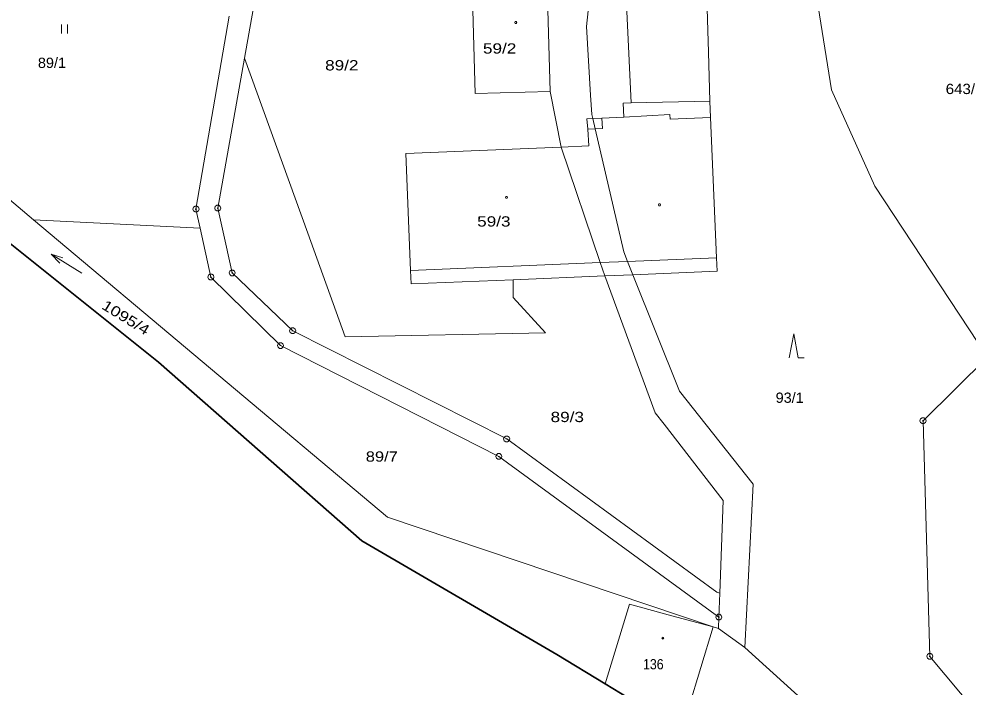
# Model space of a CAD drawing. Extents: x -687390 to -684106, y -954833 to -951648.
# Drawn here: x -687306.4 to -687149.2, y -953102.7 to -952992 of the extents above; entities that cross this region are included whole.
import ezdxf

# ---------------------------------------------------------------- set-up
doc = ezdxf.new("R2010")
doc.units = 0
doc.header["$LTSCALE"] = 0.68
doc.header["$PDMODE"] = 32
doc.header["$PDSIZE"] = 0.34
for name, color, linetype, lineweight in [('1', 7, 'Continuous', 13), ('3', 7, 'Continuous', 13), ('4', 7, 'Continuous', 13), ('5', 7, 'Continuous', 13), ('8', 7, 'Continuous', 13)]:
    doc.layers.add(name, color=color, linetype=linetype, lineweight=lineweight)
doc.layers.add('2', color=7, linetype='Continuous')

msp = doc.modelspace()

# ---------------------------------------------------------------- linework, layer by layer
at = {"layer": '1'}
for p, q in [((-687171.85, -953003.77), (-687180.3, -952950.89)), ((-687218.99, -952983.29), (-687218.44, -953004.04)), ((-687231.39, -952983.63), (-687230.83, -953004.38)), ((-687277.05, -953023.53), (-687271.54, -952991.58)), ((-687269.03, -952998.54), (-687273.44, -953023.38)), ((-687258.55, -953027.54), (-687269.03, -952998.54)), ((-687230.83, -953004.38), (-687218.44, -953004.04)), ((-687218.44, -953004.04), (-687216.6, -953013.27)), ((-687191.97, -953005.64), (-687191.86, -953008.35)), ((-687211.36, -953008.54), (-687211.52, -953007.83)), ((-687216.6, -953013.27), (-687210.15, -953032.4)), ((-687276.37, -953026.67), (-687303.95, -953025.31)), ((-687258.55, -953027.54), (-687252.33, -953044.71)), ((-687205.61, -953032.21), (-687206.24, -953030.62)), ((-687241.52, -953033.71), (-687241.43, -953035.93)), ((-687190.78, -953033.82), (-687204.73, -953034.41)), ((-687224.52, -953035.23), (-687224.56, -953038.19)), ((-687224.56, -953038.19), (-687219.21, -953044.02)), ((-687252.33, -953044.71), (-687219.21, -953044.02)), ((-687184.78, -953069.1), (-687197, -953053.68)), ((-687226.9, -953064.53), (-687190.48, -953091.15)), ((-687209.3, -953102.21), (-687205.27, -953088.97)), ((-687198.26, -953090.92), (-687205.27, -953088.97)), ((-687198.26, -953090.92), (-687191.42, -953092.75)), ((-687190.48, -953091.15), (-687190.55, -953093.04)), ((-687196.64, -953109.91), (-687191.42, -953092.75)), ((-687190.55, -953093.04), (-687186.21, -953096.15))]:
    msp.add_line(p, q, dxfattribs=at)
at = {"layer": '1', "lineweight": 35}
for p, q in [((-687283.27, -953048.91), (-687343.63, -953000.56)), ((-687283.27, -953048.91), (-687249.6, -953078.52)), ((-687217.33, -953097.33), (-687249.6, -953078.52)), ((-687217.33, -953097.33), (-687209.3, -953102.21))]:
    msp.add_line(p, q, dxfattribs=at)
at = {"layer": '1'}
for points in [[(-687269.03, -952998.54), (-687263.99, -952970.24), (-687261.03, -952965.73), (-687259.43, -952963.28)], [(-687212.39, -952993.27), (-687211.72, -952986.95), (-687215.35, -952976.69)], [(-687191.97, -953005.64), (-687192.2, -952997.53), (-687192.74, -952979.44)], [(-687211.52, -953007.83), (-687211.71, -953004.66), (-687212.39, -952993.27)], [(-687171.85, -953003.77), (-687164.64, -953019.72), (-687146.01, -953048.09), (-687124.1, -953070.77)], [(-687211.36, -953008.54), (-687210.97, -953010.24), (-687206.24, -953030.62)], [(-687190.78, -953033.82), (-687190.88, -953031.6), (-687191.86, -953008.35)], [(-687245.33, -953074.55), (-687303.95, -953025.31), (-687321.79, -953010.21)], [(-687216.6, -953013.27), (-687242.32, -953014.34), (-687241.52, -953033.71)], [(-687277.05, -953023.53), (-687276.37, -953026.67), (-687274.58, -953034.79), (-687263.05, -953046.15), (-687226.9, -953064.53)], [(-687225.61, -953061.62), (-687261.04, -953043.7), (-687271.06, -953034.1), (-687272.67, -953026.85), (-687273.44, -953023.38)], [(-687197, -953053.68), (-687204.73, -953034.41), (-687205.61, -953032.21)], [(-687210.15, -953032.4), (-687209.34, -953034.6), (-687201.01, -953057.26)], [(-687209.34, -953034.6), (-687224.52, -953035.23), (-687241.43, -953035.93)], [(-687146.01, -953048.09), (-687156.68, -953058.6), (-687155.56, -953097.64), (-687150.48, -953103.71), (-687143.97, -953111.49), (-687139.25, -953122.31), (-687131.65, -953139.03), (-687139.9, -953147.82), (-687145.6, -953153.05), (-687131.15, -953173.98), (-687112.27, -953196.97), (-687095.24, -953216.13), (-687090.69, -953245), (-687097.15, -953266.61)], [(-687201.01, -953057.26), (-687199.54, -953059.18), (-687189.78, -953071.81)], [(-687190.34, -953087.17), (-687190.8, -953086.99), (-687225.61, -953061.62)], [(-687168, -953112.71), (-687186.21, -953096.15), (-687184.78, -953069.1)], [(-687189.78, -953071.81), (-687190.34, -953087.17), (-687190.48, -953091.15)], [(-687245.33, -953074.55), (-687191.42, -953092.75), (-687190.55, -953093.04)]]:
    msp.add_lwpolyline(points, dxfattribs=at)
at = {"layer": '1', "lineweight": 35}
msp.add_lwpolyline([(-687180.98, -953119.45), (-687196.64, -953109.91), (-687209.3, -953102.21)], dxfattribs=at)
at = {"layer": '3'}
for p, q in [((-687299.34, -952992.96), (-687299.34, -952994.46)), ((-687298.34, -952994.46), (-687298.34, -952992.96)), ((-687295.938, -953034.157), (-687301.042, -953031.003))]:
    msp.add_line(p, q, dxfattribs=at)
for points in [[(-687299.604, -953032.48), (-687301.042, -953031.003), (-687299.078, -953031.629)], [(-687178.84, -953048.2), (-687178.09, -953044.2), (-687177.34, -953048.2), (-687176.34, -953048.2)]]:
    msp.add_lwpolyline(points, dxfattribs=at)
at = {"layer": '4'}
for p, q in [((-687191.97, -953005.64), (-687204.98, -953005.92)), ((-687212.18, -953010.3), (-687212.04, -953013.07)), ((-687212.04, -953013.07), (-687216.6, -953013.27)), ((-687205.61, -953032.21), (-687210.15, -953032.4)), ((-687190.88, -953031.6), (-687205.61, -953032.21)), ((-687210.15, -953032.4), (-687241.52, -953033.71)), ((-687204.73, -953034.41), (-687209.34, -953034.6))]:
    msp.add_line(p, q, dxfattribs=at)
for points in [[(-687215.9, -952960.52), (-687214.88, -952960.48), (-687214.4, -952977), (-687206.4, -952976.76), (-687204.98, -953005.92), (-687206.34, -953005.99), (-687206.22, -953008.27), (-687198.6, -953007.86)], [(-687209.84, -953008.46), (-687211.36, -953008.54), (-687212.36, -953008.59), (-687212.18, -953010.3)], [(-687206.22, -953008.27), (-687209.84, -953008.46), (-687209.75, -953010.18)], [(-687191.86, -953008.35), (-687198.56, -953008.64), (-687198.6, -953007.86)], [(-687209.75, -953010.18), (-687210.97, -953010.24), (-687212.18, -953010.3)]]:
    msp.add_lwpolyline(points, dxfattribs=at)
at = {"layer": '5'}
for points in [[(-687224.02, -952992.47), (-687223.93, -952992.62), (-687224.02, -952992.77), (-687224.2, -952992.77), (-687224.29, -952992.62), (-687224.2, -952992.47)], [(-687225.55, -953021.42), (-687225.46, -953021.57), (-687225.55, -953021.72), (-687225.73, -953021.72), (-687225.82, -953021.57), (-687225.73, -953021.42)], [(-687200.23, -953022.68), (-687200.14, -953022.83), (-687200.23, -953022.98), (-687200.41, -953022.98), (-687200.5, -953022.83), (-687200.41, -953022.68)]]:
    msp.add_lwpolyline(points, close=True, dxfattribs=at)
msp.add_point((-687199.76, -953094.63), dxfattribs=at)
at = {"layer": '8'}
for p, q in [((-687277.17, -953023.53), (-687276.93, -953023.53)), ((-687273.56, -953023.38), (-687273.32, -953023.38)), ((-687274.7, -953034.79), (-687274.46, -953034.79)), ((-687271.18, -953034.1), (-687270.94, -953034.1)), ((-687261.16, -953043.7), (-687260.92, -953043.7)), ((-687263.17, -953046.15), (-687262.93, -953046.15)), ((-687156.8, -953058.6), (-687156.56, -953058.6)), ((-687225.73, -953061.62), (-687225.49, -953061.62)), ((-687227.02, -953064.53), (-687226.78, -953064.53)), ((-687190.6, -953091.15), (-687190.36, -953091.15)), ((-687155.68, -953097.64), (-687155.44, -953097.64))]:
    msp.add_line(p, q, dxfattribs=at)
for points in [[(-687276.9, -953023.05), (-687276.65, -953023.23), (-687276.55, -953023.52), (-687276.65, -953023.81), (-687276.9, -953023.99), (-687277.21, -953023.99), (-687277.46, -953023.81), (-687277.56, -953023.52), (-687277.46, -953023.23), (-687277.21, -953023.05)], [(-687273.29, -953022.9), (-687273.04, -953023.08), (-687272.94, -953023.37), (-687273.04, -953023.66), (-687273.29, -953023.84), (-687273.6, -953023.84), (-687273.85, -953023.66), (-687273.95, -953023.37), (-687273.85, -953023.08), (-687273.6, -953022.9)], [(-687270.91, -953033.62), (-687270.66, -953033.8), (-687270.56, -953034.09), (-687270.66, -953034.38), (-687270.91, -953034.56), (-687271.22, -953034.56), (-687271.47, -953034.38), (-687271.57, -953034.09), (-687271.47, -953033.8), (-687271.22, -953033.62)], [(-687274.43, -953034.31), (-687274.18, -953034.49), (-687274.08, -953034.78), (-687274.18, -953035.07), (-687274.43, -953035.25), (-687274.74, -953035.25), (-687274.99, -953035.07), (-687275.09, -953034.78), (-687274.99, -953034.49), (-687274.74, -953034.31)], [(-687260.89, -953043.22), (-687260.64, -953043.4), (-687260.54, -953043.69), (-687260.64, -953043.98), (-687260.89, -953044.16), (-687261.2, -953044.16), (-687261.45, -953043.98), (-687261.55, -953043.69), (-687261.45, -953043.4), (-687261.2, -953043.22)], [(-687262.9, -953045.67), (-687262.65, -953045.85), (-687262.55, -953046.14), (-687262.65, -953046.43), (-687262.9, -953046.61), (-687263.21, -953046.61), (-687263.46, -953046.43), (-687263.56, -953046.14), (-687263.46, -953045.85), (-687263.21, -953045.67)], [(-687156.53, -953058.12), (-687156.28, -953058.3), (-687156.18, -953058.59), (-687156.28, -953058.88), (-687156.53, -953059.06), (-687156.84, -953059.06), (-687157.09, -953058.88), (-687157.19, -953058.59), (-687157.09, -953058.3), (-687156.84, -953058.12)], [(-687225.46, -953061.14), (-687225.21, -953061.32), (-687225.11, -953061.61), (-687225.21, -953061.9), (-687225.46, -953062.08), (-687225.77, -953062.08), (-687226.02, -953061.9), (-687226.12, -953061.61), (-687226.02, -953061.32), (-687225.77, -953061.14)], [(-687226.75, -953064.05), (-687226.5, -953064.23), (-687226.4, -953064.52), (-687226.5, -953064.81), (-687226.75, -953064.99), (-687227.06, -953064.99), (-687227.31, -953064.81), (-687227.41, -953064.52), (-687227.31, -953064.23), (-687227.06, -953064.05)], [(-687190.33, -953090.67), (-687190.08, -953090.85), (-687189.98, -953091.14), (-687190.08, -953091.43), (-687190.33, -953091.61), (-687190.64, -953091.61), (-687190.89, -953091.43), (-687190.99, -953091.14), (-687190.89, -953090.85), (-687190.64, -953090.67)], [(-687155.41, -953097.16), (-687155.16, -953097.34), (-687155.06, -953097.63), (-687155.16, -953097.92), (-687155.41, -953098.1), (-687155.72, -953098.1), (-687155.97, -953097.92), (-687156.07, -953097.63), (-687155.97, -953097.34), (-687155.72, -953097.16)]]:
    msp.add_lwpolyline(points, close=True, dxfattribs=at)

# ---------------------------------------------------------------- texts
at = {"layer": '2'}
for s, width, p in [('59/2', 1.25, (-687229.545, -952997.76)), ('89/1', 1.05, (-687303.225, -953000.14)), ('89/2', 1.25, (-687255.675, -953000.55)), ('643/1', 1.1, (-687152.936, -953004.47)), ('59/3', 1.25, (-687230.505, -953026.42)), ('93/1', 1.05, (-687181.085, -953055.63)), ('89/3', 1.25, (-687218.345, -953058.82)), ('89/7', 1.2, (-687248.945, -953065.38)), ('136', 0.9, (-687203.045, -953099.79))]:
    msp.add_text(s, height=1.7, dxfattribs=dict(at, width=width)).set_placement(p)
at = {"layer": '2', "width": 1.25}
msp.add_text('1095/4', height=1.7, rotation=328.419, dxfattribs=at).set_placement((-687292.811, -953039.941))

doc.saveas('drawing.dxf')
